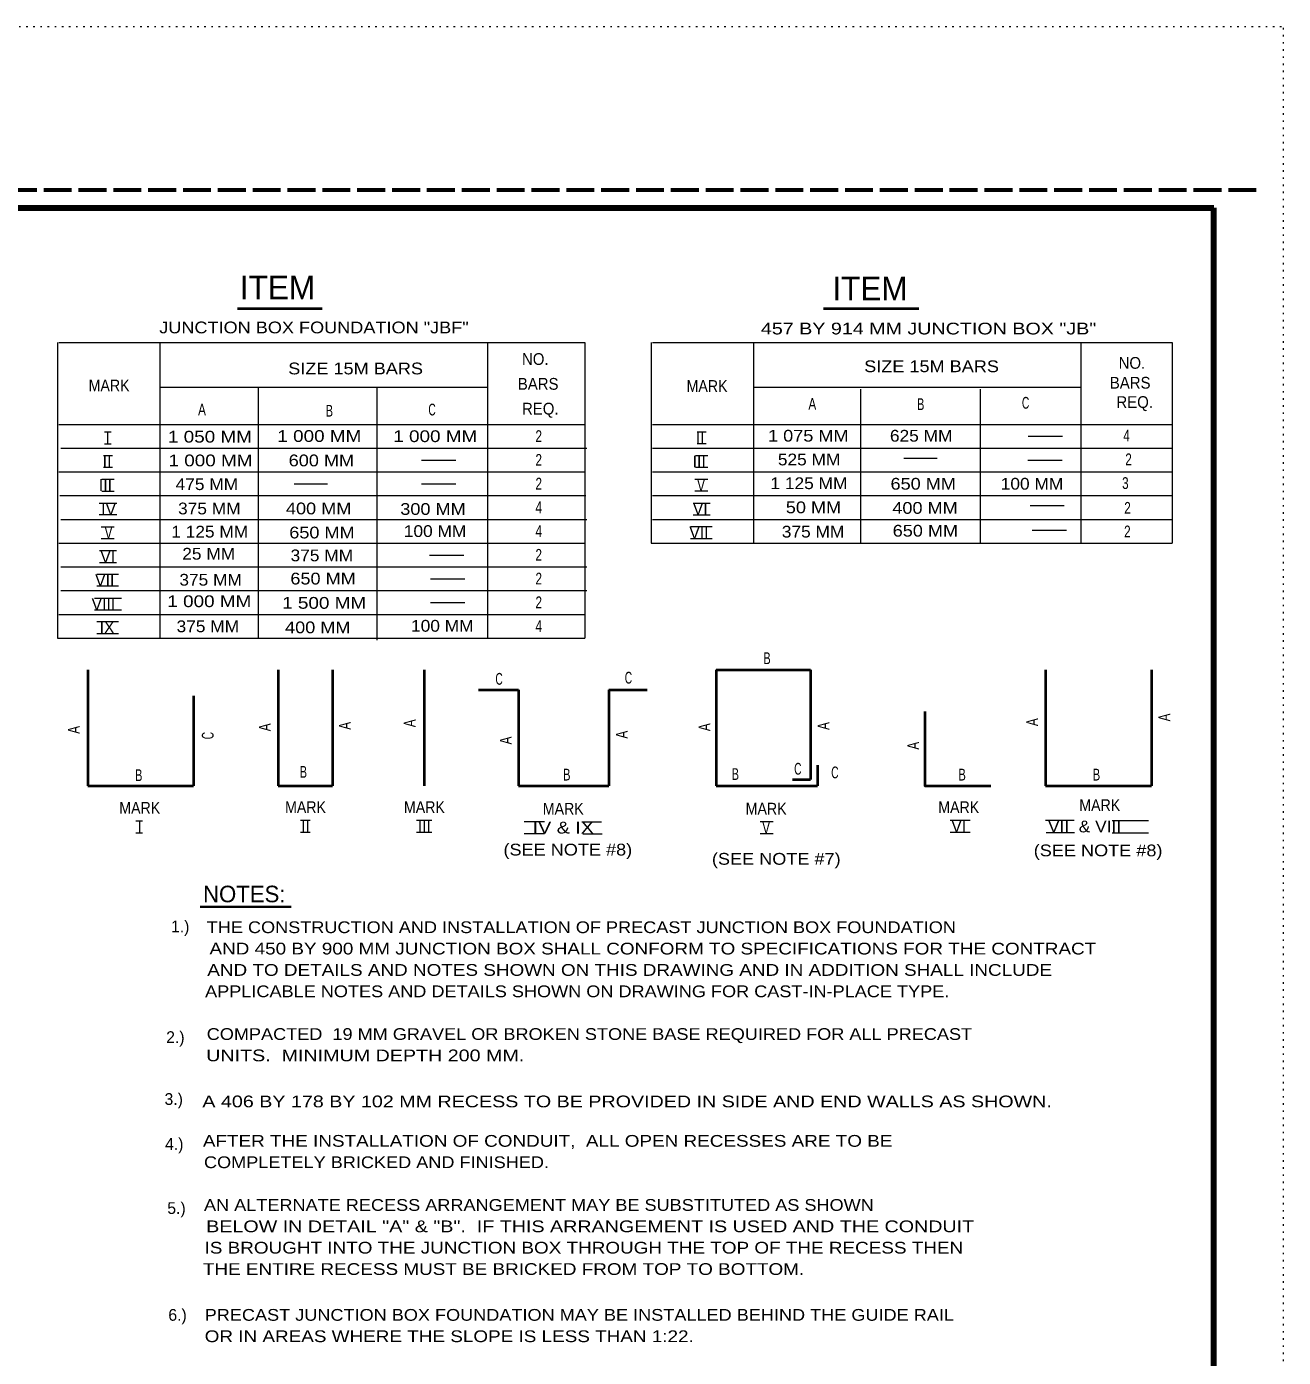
# Model space of a CAD drawing. Extents: x 312583 to 312854, y 144419 to 144597.
# Drawn here: x 312772.3 to 312853.5, y 144510.8 to 144596.8 of the extents above; entities that cross this region are included whole.
import ezdxf
from ezdxf.enums import TextEntityAlignment as Align

# ---------------------------------------------------------------- set-up
doc = ezdxf.new("R2010")
doc.units = 0
doc.header["$LTSCALE"] = 0.3
doc.linetypes.add('DOTTED', pattern=[1.5, 0.3, -1.2])
doc.linetypes.add('LONG_DASHED', pattern=[7.5, 6, -1.5])
for name, color, linetype, lineweight in [('1', 7, 'Continuous', 25), ('2', 7, 'Continuous', 13), ('63', 7, 'DOTTED', 13)]:
    doc.layers.add(name, color=color, linetype=linetype, lineweight=lineweight)

msp = doc.modelspace()

# ---------------------------------------------------------------- linework, layer by layer
at = {"layer": '1', "linetype": 'LONG_DASHED', "lineweight": 60}
msp.add_line((312851.75, 144586.2246), (312583.526, 144586.2246), dxfattribs=at)
at = {"layer": '1', "lineweight": 158}
msp.add_line((312849, 144423.1446), (312849, 144585.0846), dxfattribs=at)
at = {"layer": '1', "lineweight": 13}
for p, q in [((312774.3506, 144576.3859), (312774.3506, 144557.2883)), ((312774.4272, 144576.3859), (312808.3906, 144576.3859)), ((312780.9592, 144576.3859), (312780.9592, 144557.2883)), ((312802.1039, 144576.3859), (312802.1039, 144557.2883)), ((312808.3906, 144576.3859), (312808.3906, 144557.2883)), ((312812.6753, 144576.3859), (312812.6753, 144563.4216)), ((312812.752, 144576.3859), (312846.3243, 144576.3859)), ((312819.284, 144576.3859), (312819.284, 144563.4216)), ((312840.4287, 144576.3859), (312840.4287, 144563.4216)), ((312846.3243, 144576.3859), (312846.3243, 144563.4216)), ((312780.9592, 144573.5033), (312802.1039, 144573.5033)), ((312787.2919, 144573.5033), (312787.2919, 144557.2883)), ((312794.9586, 144573.5033), (312794.9586, 144557.1579)), ((312819.284, 144573.5033), (312840.4287, 144573.5033)), ((312826.1993, 144573.3729), (312826.1993, 144563.4216)), ((312833.912, 144573.3729), (312833.912, 144563.4216)), ((312774.4272, 144571.0883), (312808.3906, 144571.0883)), ((312812.752, 144571.0883), (312846.3243, 144571.0883)), ((312837.017, 144570.3216), (312839.2327, 144570.3216)), ((312774.5576, 144569.5549), (312808.5209, 144569.5549)), ((312812.752, 144569.5549), (312846.3243, 144569.5549)), ((312797.8489, 144568.7883), (312800.0646, 144568.7883)), ((312828.9823, 144568.9186), (312831.152, 144568.9186)), ((312837.0093, 144568.7806), (312839.225, 144568.7806)), ((312774.4272, 144568.0216), (312808.3906, 144568.0216)), ((312812.752, 144568.0216), (312846.3243, 144568.0216)), ((312789.6149, 144567.2549), (312791.7846, 144567.2549)), ((312797.8412, 144567.2549), (312800.0569, 144567.2549)), ((312774.4886, 144566.4883), (312808.4519, 144566.4883)), ((312812.752, 144566.4883), (312846.3243, 144566.4883)), ((312837.1397, 144565.8519), (312839.3553, 144565.8519)), ((312774.5576, 144564.9549), (312808.5209, 144564.9549)), ((312812.752, 144564.9549), (312846.3243, 144564.9549)), ((312837.27, 144564.2573), (312839.4857, 144564.2573)), ((312774.4272, 144563.4216), (312808.3906, 144563.4216)), ((312812.6753, 144563.4216), (312846.3243, 144563.4216)), ((312798.3626, 144562.6549), (312800.5782, 144562.6549)), ((312774.5576, 144561.8883), (312808.5209, 144561.8883)), ((312798.4239, 144561.1216), (312800.6396, 144561.1216)), ((312774.5576, 144560.3549), (312808.5209, 144560.3549)), ((312798.4239, 144559.5883), (312800.6396, 144559.5883)), ((312774.4272, 144558.8216), (312808.3906, 144558.8216)), ((312774.3506, 144557.2883), (312808.3906, 144557.2883))]:
    msp.add_line(p, q, dxfattribs=at)
at = {"layer": '1', "lineweight": 40}
for p, q in [((312776.2896, 144555.2336), (312776.2896, 144547.7509)), ((312788.5844, 144555.2336), (312788.5844, 144547.7509)), ((312792.0957, 144555.2336), (312792.0957, 144547.7509)), ((312798.0144, 144555.2336), (312798.0144, 144547.7509)), ((312816.8667, 144555.2336), (312816.8667, 144547.7509)), ((312816.8667, 144555.2336), (312822.9617, 144555.2336)), ((312822.9617, 144555.2336), (312822.9617, 144548.1573)), ((312838.1363, 144555.2336), (312838.1363, 144547.7509)), ((312844.975, 144555.2336), (312844.975, 144547.7509)), ((312801.5257, 144553.9379), (312804.1094, 144553.9379)), ((312804.1094, 144553.9379), (312804.1094, 144547.7509)), ((312809.936, 144553.9379), (312809.936, 144547.7509)), ((312809.936, 144553.9379), (312812.4277, 144553.9379)), ((312783.1283, 144553.5623), (312783.1283, 144547.7509)), ((312823.4217, 144549.0696), (312823.4217, 144547.7509)), ((312821.804, 144548.1573), (312822.9617, 144548.1573)), ((312776.2896, 144547.7509), (312783.1283, 144547.7509)), ((312788.5844, 144547.7509), (312792.0957, 144547.7509)), ((312804.1094, 144547.7509), (312809.936, 144547.7509)), ((312816.8667, 144547.7509), (312823.4217, 144547.7509)), ((312838.1363, 144547.7509), (312844.975, 144547.7509))]:
    msp.add_line(p, q, dxfattribs=at)
at = {"layer": '1', "lineweight": 158}
msp.add_lwpolyline([(312616.5, 144423.1446), (312616.5, 144585.0846), (312849, 144585.0846)], dxfattribs=at)
at = {"layer": '1', "lineweight": 40}
msp.add_lwpolyline([(312830.3524, 144552.5503), (312830.3524, 144547.7509), (312834.6074, 144547.7509)], dxfattribs=at)
at = {"layer": '2', "lineweight": 40}
for p, q in [((312785.9732, 144578.5863), (312791.4369, 144578.5863)), ((312823.7944, 144578.5863), (312829.9599, 144578.5863))]:
    msp.add_line(p, q, dxfattribs=at)
at = {"layer": '2'}
for p, q in [((312777.3866, 144570.6136), (312777.8159, 144570.6136)), ((312815.6423, 144570.6011), (312816.2173, 144570.6011)), ((312777.3866, 144569.8463), (312777.8159, 144569.8463)), ((312815.6423, 144569.8539), (312816.2173, 144569.8539)), ((312777.3176, 144569.0729), (312777.8926, 144569.0729)), ((312815.535, 144569.0878), (312816.3323, 144569.0878)), ((312777.3176, 144568.3206), (312777.8926, 144568.3206)), ((312815.535, 144568.3206), (312816.3323, 144568.3206)), ((312777.2102, 144567.5491), (312778.0076, 144567.5491)), ((312777.2102, 144566.7873), (312778.0076, 144566.7873)), ((312815.4967, 144567.5629), (312816.3323, 144567.5629)), ((312815.4967, 144566.7949), (312816.3323, 144566.7949)), ((312777.0339, 144565.9996), (312778.1686, 144565.9996)), ((312815.3817, 144566.0139), (312816.4857, 144566.0139)), ((312777.0339, 144565.2616), (312778.1686, 144565.2616)), ((312815.3817, 144565.2463), (312816.4857, 144565.2463)), ((312777.1719, 144564.4766), (312778.0076, 144564.4766)), ((312815.213, 144564.4903), (312816.6083, 144564.4903)), ((312777.1719, 144563.7283), (312778.0076, 144563.7283)), ((312815.213, 144563.7206), (312816.6083, 144563.7206)), ((312777.0569, 144562.9437), (312778.1609, 144562.9437)), ((312777.0569, 144562.1796), (312778.1609, 144562.1796)), ((312776.8882, 144561.4129), (312778.2836, 144561.4129)), ((312776.7349, 144559.8628), (312778.4676, 144559.8628)), ((312776.8882, 144560.6539), (312778.2836, 144560.6539)), ((312776.7349, 144559.1129), (312778.4676, 144559.1129)), ((312776.8882, 144558.3556), (312778.2836, 144558.3556)), ((312776.8882, 144557.5873), (312778.2836, 144557.5873)), ((312779.41, 144545.487), (312779.824, 144545.487)), ((312790.0334, 144545.521), (312790.662, 144545.521)), ((312797.5237, 144545.5353), (312798.5204, 144545.5353)), ((312804.4774, 144545.4433), (312805.796, 144545.4433)), ((312808.1904, 144545.4256), (312809.4784, 144545.4256)), ((312819.711, 144545.4433), (312820.5544, 144545.4433)), ((312831.9777, 144545.5353), (312833.281, 144545.5353)), ((312838.1412, 144545.5176), (312839.9889, 144545.5176)), ((312842.4373, 144545.4999), (312844.791, 144545.4999)), ((312779.41, 144544.7068), (312779.824, 144544.7068)), ((312790.0334, 144544.763), (312790.662, 144544.763)), ((312797.5237, 144544.7542), (312798.5204, 144544.7542)), ((312804.4774, 144544.658), (312805.796, 144544.658)), ((312808.2565, 144544.6492), (312809.5139, 144544.6492)), ((312819.711, 144544.6606), (312820.5544, 144544.6606)), ((312831.9777, 144544.7569), (312833.281, 144544.7569)), ((312838.1767, 144544.7271), (312840.0091, 144544.7271)), ((312842.4373, 144544.7183), (312844.791, 144544.7183))]:
    msp.add_line(p, q, dxfattribs=at)
at = {"layer": '2', "lineweight": 35}
msp.add_line((312783.5564, 144539.9274), (312789.4214, 144539.9274), dxfattribs=at)
at = {"layer": '63'}
msp.add_line((312601.2, 144596.7846), (312853.5, 144596.7846), dxfattribs=at)
msp.add_lwpolyline([(312601.2, 144418.5846), (312853.5, 144418.5846), (312853.5, 144596.7846)], dxfattribs=at)

# ---------------------------------------------------------------- texts
at = {"layer": '2'}
for s, height, p in [('ITEM', 1.52, (312788.5491, 144579.1748)), ('ITEM', 1.52, (312826.8031, 144579.104)), ('II', 0.76, (312790.3577, 144544.7668)), ('III', 0.76, (312798.0321, 144544.7668)), ('VI', 0.76, (312832.5358, 144544.7668)), ('NOTES:', 1.07, (312786.4019, 144540.2242))]:
    msp.add_text(s, height=height, dxfattribs=at).set_placement(p, align=Align.CENTER)
for s, width, p in [('JUNCTION BOX FOUNDATION "JBF"', 1.15, (312780.9107, 144576.9724)), ('457 BY 914 MM JUNCTION BOX "JB"', 1.25, (312819.763, 144576.9015)), ('NO.', 0.95, (312804.3357, 144574.9321)), ('NO.', 0.95, (312842.8605, 144574.6839)), ('SIZE 15M BARS', 1.15, (312789.2402, 144574.3226)), ('SIZE 15M BARS', 1.15, (312826.431, 144574.4644)), ('MARK', 0.9, (312776.3542, 144573.2243)), ('BARS', 0.95, (312804.0653, 144573.3298)), ('MARK', 0.9, (312814.9625, 144573.1889)), ('BARS', 0.95, (312842.2933, 144573.4008)), ('A', 0.75, (312822.828, 144572.0342)), ('B', 0.7, (312829.8414, 144572.0189)), ('C', 0.65, (312836.616, 144572.1051)), ('REQ.', 0.95, (312842.7182, 144572.1532)), ('A', 0.75, (312783.4183, 144571.67)), ('B', 0.7, (312791.6584, 144571.5933)), ('C', 0.65, (312798.29, 144571.67)), ('REQ.', 0.95, (312804.3352, 144571.7275)), ('I', 0.85, (312777.4626, 144569.8543)), ('1 050 MM', 1.2, (312781.4726, 144569.9162)), ('1 000 MM', 1.2, (312788.537, 144569.9594)), ('1 000 MM', 1.2, (312796.0245, 144569.9489)), ('2', 0.75, (312805.2043, 144569.9517)), ('1 075 MM', 1.15, (312820.2239, 144569.9776)), ('625 MM', 1.1, (312828.0936, 144569.9775)), ('4', 0.75, (312843.1602, 144569.9872)), ('1 000 MM', 1.2, (312781.5078, 144568.383)), ('600 MM', 1.15, (312789.2697, 144568.383)), ('2', 0.75, (312805.2043, 144568.4184)), ('525 MM', 1.1, (312820.8569, 144568.4442)), ('2', 0.75, (312843.2905, 144568.4539)), ('475 MM', 1.1, (312781.9686, 144566.8496)), ('2', 0.75, (312805.2043, 144566.885)), ('1 125 MM', 1.1, (312820.38, 144566.9109)), ('650 MM', 1.15, (312828.1324, 144566.8756)), ('100 MM', 1.1, (312835.249, 144566.8755)), ('3', 0.75, (312843.0835, 144566.9205)), ('V', 0.75, (312815.6441, 144566.7874)), ('375 MM', 1.1, (312782.126, 144565.2807)), ('400 MM', 1.15, (312789.0938, 144565.2808)), ('300 MM', 1.15, (312796.4765, 144565.2454)), ('4', 0.75, (312805.2043, 144565.3517)), ('50 MM', 1.15, (312821.3719, 144565.3517)), ('400 MM', 1.15, (312828.2493, 144565.3163)), ('2', 0.75, (312843.2215, 144565.3182)), ('V', 0.75, (312777.3814, 144563.7209)), ('1 125 MM', 1.1, (312781.6872, 144563.7829)), ('650 MM', 1.15, (312789.3072, 144563.7272)), ('100 MM', 1.1, (312796.7048, 144563.8184)), ('4', 0.75, (312805.2043, 144563.8184)), ('375 MM', 1.1, (312821.1127, 144563.783)), ('650 MM', 1.15, (312828.2713, 144563.8434)), ('2', 0.75, (312843.2139, 144563.7925)), ('25 MM', 1.1, (312782.398, 144562.3559)), ('375 MM', 1.1, (312789.3916, 144562.2496)), ('2', 0.75, (312805.2043, 144562.285)), ('375 MM', 1.1, (312782.21, 144560.676)), ('650 MM', 1.15, (312789.3781, 144560.7517)), ('2', 0.75, (312805.2043, 144560.7517)), ('1 000 MM', 1.2, (312781.4339, 144559.2893)), ('1 500 MM', 1.2, (312788.8482, 144559.1829)), ('2', 0.75, (312805.2043, 144559.2184)), ('375 MM', 1.1, (312782.03, 144557.6677)), ('400 MM', 1.15, (312789.0363, 144557.5997)), ('100 MM', 1.1, (312797.171, 144557.7004)), ('4', 0.75, (312805.2043, 144557.685)), ('B', 0.7, (312819.9196, 144555.6074)), ('C', 0.65, (312802.6178, 144554.2763)), ('C', 0.65, (312810.9707, 144554.3472)), ('B', 0.7, (312779.3502, 144548.0538)), ('B', 0.7, (312789.9814, 144548.2666)), ('B', 0.7, (312806.9927, 144548.0893)), ('B', 0.7, (312817.8738, 144548.1248)), ('C', 0.65, (312821.9101, 144548.4669)), ('C', 0.65, (312824.3012, 144548.2302)), ('B', 0.7, (312832.5208, 144548.0893)), ('B', 0.7, (312841.1969, 144548.0893)), ('MARK', 0.9, (312840.323, 144546.1198)), ('VII  & VIII', 1.1, (312838.301, 144544.7399)), ('(SEE NOTE #8)', 1.15, (312803.1378, 144543.2449)), ('(SEE NOTE #8)', 1.15, (312837.3793, 144543.1936)), ('(SEE NOTE #7)', 1.15, (312816.5995, 144542.6495)), ('THE CONSTRUCTION AND INSTALLATION OF PRECAST JUNCTION BOX FOUNDATION  ', 1.15, (312783.9789, 144538.2321)), ('AND 450 BY 900 MM JUNCTION BOX SHALL CONFORM TO SPECIFICATIONS FOR THE CONTRACT  ', 1.2, (312784.156, 144536.8521)), ('AND TO DETAILS AND NOTES SHOWN ON THIS DRAWING AND IN ADDITION SHALL INCLUDE   ', 1.2, (312784.0143, 144535.4721)), ('APPLICABLE NOTES AND DETAILS SHOWN ON DRAWING FOR CAST-IN-PLACE TYPE.  ', 1.15, (312783.8726, 144534.0921)), ('COMPACTED  19 MM GRAVEL OR BROKEN STONE BASE REQUIRED FOR ALL PRECAST  ', 1.15, (312783.9788, 144531.3321)), ('UNITS.  MINIMUM DEPTH 200 MM.  ', 1.25, (312783.9435, 144529.9521)), ('A 406 BY 178 BY 102 MM RECESS TO BE PROVIDED IN SIDE AND END WALLS AS SHOWN.  ', 1.25, (312783.6954, 144526.9794)), ('AFTER THE INSTALLATION OF CONDUIT,  ALL OPEN RECESSES ARE TO BE  ', 1.2, (312783.7308, 144524.4321)), ('COMPLETELY BRICKED AND FINISHED. ', 1.15, (312783.8017, 144523.0521)), ('AN ALTERNATE RECESS ARRANGEMENT MAY BE SUBSTITUTED AS SHOWN  ', 1.15, (312783.8017, 144520.2921)), ('BELOW IN DETAIL "A" & "B".  IF THIS ARRANGEMENT IS USED AND THE CONDUIT  ', 1.25, (312783.9432, 144518.9121)), ('IS BROUGHT INTO THE JUNCTION BOX THROUGH THE TOP OF THE RECESS THEN   ', 1.2, (312783.8371, 144517.5321)), ('THE ENTIRE RECESS MUST BE BRICKED FROM TOP TO BOTTOM.   ', 1.2, (312783.7308, 144516.1521)), ('PRECAST JUNCTION BOX FOUNDATION MAY BE INSTALLED BEHIND THE GUIDE RAIL', 1.15, (312783.8478, 144513.1928)), ('OR IN AREAS WHERE THE SLOPE IS LESS THAN 1:22.', 1.2, (312783.8478, 144511.8128))]:
    msp.add_text(s, height=0.76, dxfattribs=dict(at, width=width)).set_placement(p)
for s, p in [('II', (312815.559, 144569.8542)), ('II', (312777.2608, 144568.312)), ('III', (312815.356, 144568.3209)), ('III', (312777.0135, 144566.7963)), ('IV', (312777.1618, 144565.2541)), ('VI', (312815.3665, 144565.263)), ('VII', (312815.1382, 144563.7209)), ('VI', (312777.1039, 144562.1698)), ('VII', (312776.7692, 144560.6541)), ('VIII', (312776.5407, 144559.1055)), ('IX', (312777.06, 144557.5964)), ('1.)  ', (312781.6723, 144538.281)), ('2.)  ', (312781.3601, 144531.1328)), ('3.)  ', (312781.2538, 144527.1347)), ('4.)  ', (312781.2893, 144524.2328)), ('5.)  ', (312781.4311, 144520.0928)), ('6.)  ', (312781.4994, 144513.1928))]:
    msp.add_text(s, height=0.76, dxfattribs=at).set_placement(p)
for s, width, p in [('A', 0.75, (312846.195, 144551.9079)), ('A', 0.75, (312775.7746, 144551.1066)), ('A', 0.75, (312788.1048, 144551.2706)), ('A', 0.75, (312793.2802, 144551.3692)), ('A', 0.75, (312797.4639, 144551.5322)), ('A', 0.75, (312811.156, 144550.7962)), ('A', 0.75, (312816.4934, 144551.2783)), ('A', 0.75, (312824.1817, 144551.3559)), ('A', 0.75, (312837.6567, 144551.6031)), ('C', 0.65, (312784.4241, 144550.7492)), ('A', 0.75, (312803.6652, 144550.4205)), ('A', 0.75, (312829.9791, 144550.0813))]:
    msp.add_text(s, height=0.76, rotation=90, dxfattribs=dict(at, width=width)).set_placement(p)
for s, width, p in [('MARK', 0.9, (312779.6524, 144545.9426)), ('MARK', 0.9, (312790.3577, 144545.9868)), ('MARK', 0.9, (312798.0321, 144545.9868)), ('MARK', 0.9, (312807.0012, 144545.8859)), ('MARK', 0.9, (312820.0997, 144545.8886)), ('MARK', 0.9, (312832.5358, 144545.9868)), ('I', 0.85, (312779.6523, 144544.7226)), ('IV & IX', 1.25, (312807.0012, 144544.6659)), ('V', 0.75, (312820.0997, 144544.6686))]:
    msp.add_text(s, height=0.76, dxfattribs=dict(at, width=width)).set_placement(p, align=Align.CENTER)

doc.saveas('drawing.dxf')
